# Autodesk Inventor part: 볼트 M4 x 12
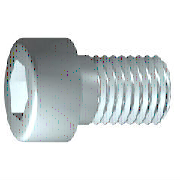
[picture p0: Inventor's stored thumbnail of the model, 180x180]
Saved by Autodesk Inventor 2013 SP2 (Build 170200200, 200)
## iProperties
IsCustomPart: 0
Created: 2012-02
Part Number: 볼트 M4 x 12
Material: 스테인리스강
Description: 6각 소켓 머리 캡 나사
Document SubType Name: Modeling
Standard: ISO 4762
Designer: mduedu
Standard Revision: Fourth edition 2004-03-01
Standards Organization: ISO
Language: ko-KR
Size Designation: M4 x 12
Categories: <MemberInstance><Categories><Category DisplayName="조임쇠" InternalName="e4da775c-781d-43d5-af7c-5136215cf5a6" Mnemonic="FSTN"><Category DisplayName="볼트" InternalN
Density: 8.08 g/cm^3
Author: mduedu
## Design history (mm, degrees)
sketch "스케치1"
  geometry: L1 (-1, 0)-(12, 0); L2 (12, 0)-(12, 2); L3 (12, 2)-(1.75, 2); L4 (1.75, 2)-(1.32, 2); L5 (1.32, 2)-(0, 2); L6 (0, 2)-(0, 3.5); L7 (0, 3.5)-(-4, 3.5); L8 (-4, 3.5)-(-4, 1.732); L9 (-4, 1.732)-(-2, 1.732); L10 (-2, 1.732)-(-1, 0); L11 (-7.2, 0)-(15.2, 0) reference; L12 (0, -0.7)-(0, 4.2) reference; L13 (1.75, 2)-(0, 2)
  constraints: 22 end point, 6 parallel, 2 collinear, 2 perpendicular, 1 horizontal, 1 point on line
  dimensions: "d1" = 10.25 distance from line of L3.end L2 (= GEL); "d2" = 0.42952 distance of L4.end L3.end (computed from GAL); "d3" = 4 distance between parallel lines of L8 L6 (= KOH); "d4" = 2 distance of L8.end L9.end (= INTI); "d5" = 60 deg angle of L10 L1; "d6" = 4 diameter of L3 L1 (= GD); "d7" = 4 diameter of L5 L1 (= BDM); "d8" = 3.4641 diameter of L9 L1 (= 1.1547 x SW); "d9" = 7 diameter of L7 L1 (= KOD); "d26" = 12 distance between parallel lines of L12 L2 (= NLG)
revolve "본체" sketch "스케치1" stored, may be unused: angle "d10" = 90 deg
sketch "스케치2"
  geometry: L1 (0, -4.9)-(0, 4.9) reference; L2 (-4.9, 0)-(4.9, 0) reference; L3 (1.732, 0)-(0.866, -1.5); L4 (0.866, -1.5)-(-0.866, -1.5); L5 (-0.866, -1.5)-(-1.732, 0); L6 (-1.732, 0)-(-0.866, 1.5); L7 (-0.866, 1.5)-(0.866, 1.5); L8 (0.866, 1.5)-(1.732, 0); 2 further points
  constraints: 12 end point, 1 coincident, 1 horizontal alignment, 1 point on line, 12 other
extrude "슬롯" join sketch "스케치2" stored distance "d11" = 10; taper "d12" = 0 deg
workplane "Work Plane1"
fillet "Fillet2" dims "d30" = 0.1 (= R)
body "Solid1"
fillet "모깎기1" dims "d17" = 0.4 (= RR)
feature "스레드" dims "d13" = 10.25 (= GEL), "d14" = 0
chamfer "모따기1" distance "d15" = 0.42941 (= -0.5 x SPD + 0.5 x GD); stored, may be unused: second distance "d16" = 0.42941 (= GUL), angle "d27" = 45 deg
other parameters: "GD" = 4 [user parameter; used in 2 equation terms], "NLG" = 12 [user parameter; used in 1 equation term], "GEL" = 10.25 [user parameter; used in 2 equation terms], "KOD" = 7 [user parameter; used in 1 equation term], "KOH" = 4 [user parameter; used in 1 equation term], "INTI" = 2 [user parameter; used in 1 equation term], "GAL" = 0.42941 (= 0.61345 x PTC) [user parameter; used in 1 equation term], "GUL" = 0.42941 (= 0.61345 x PTC) [user parameter; used in 1 equation term], "BDM" = 4 (= NND) [user parameter; used in 1 equation term], "SW" = 3 [user parameter; used in 2 equation terms], "RR" = 0.4 [user parameter; used in 1 equation term], "SPD" = 3.14117 (= NND - 1.2269 x PTC) [user parameter; used in 1 equation term], "d19" = 0, "d28" = 0, "d29" = 0, "R" = 0.1 [user parameter; used in 1 equation term], "TOA" = 30 deg [user parameter], "GD1" = 3.14117 (= THREADDIA - 1.2269 x PTC) [user parameter], "THREADDIA" = 4 [user parameter; used in 1 equation term], "FAWI" = 45 deg [user parameter], "TPU" = 14.28571 (computed from PTC) [user parameter], "PTC" = 0.7 [user parameter; used in 5 equation terms], "NND" = 4 [user parameter; used in 2 equation terms], "E0" = 3.465 (= 1.155 x SW) [user parameter]
